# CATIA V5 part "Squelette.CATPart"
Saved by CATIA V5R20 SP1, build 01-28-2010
Part number: Squelette_de_construction
Publications: "Largeur", "Longueur_couli", "Epaisseur", "Plan_de_ref", "Point.1", "Point.2", "Point.3", "Point.4", "Longueur_gliss", "Longueur_Axe", "Longueur_bielle", "Point_coulisseau2", "Point_coulisseau1"
Bounding box of the stored display mesh (mm): x -85 to 85, y -60.104 to 60.104, z 0 to 0
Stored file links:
  C:\Users\Nikow\Documents\IAO\Mécanisme IAO avec squelette\nsarlin\Squelette.CATPart

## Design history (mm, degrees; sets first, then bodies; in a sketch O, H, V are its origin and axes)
Parameters
  Largeur = 7 mm
  Longueur_gliss = 170 mm
  Longueur_couli = 20 mm
  Epaisseur = 20 mm
  Longueur_Axe = 8 mm
  Longueur_bielle = 50 mm
  Alpha = 45 deg
Body1 (main body)
  Plane1 "Plan_de_ref": type Offset, RefPlane xy-plane, Offset 0
  Point1: type OnPlane, Support Plane1, H -85 {= -Longueur_gliss /2}, V 0, Direction (1, 0, 0)
  Point2: type OnPlane, Support Plane1, H 85 {= Longueur_gliss /2}, V 0, Direction (1, 0, 0)
  Point3: type OnPlane, Support Plane1, H -60.1041 {= -Longueur_gliss /2*cos(Alpha )}, V 60.1041 {= Longueur_gliss /2*sin(Alpha )}, Direction (1, 0, 0)
  Point4: type OnPlane, Support Plane1, H 60.1041 {= Longueur_gliss /2*cos(Alpha )}, V -60.1041 {= -Longueur_gliss /2*sin(Alpha )}, Direction (1, 0, 0)
  Point5 "Point_coulisseau1": type OnPlane, Support Plane1, H -50 {= -Longueur_bielle}, V 0, Direction (1, 0, 0)
  Point6 "Point_coulisseau2": type OnPlane, Support Plane1, RefPoint Point5, H 50 {= Longueur_bielle}, V 0, Direction (1, 0, 0)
